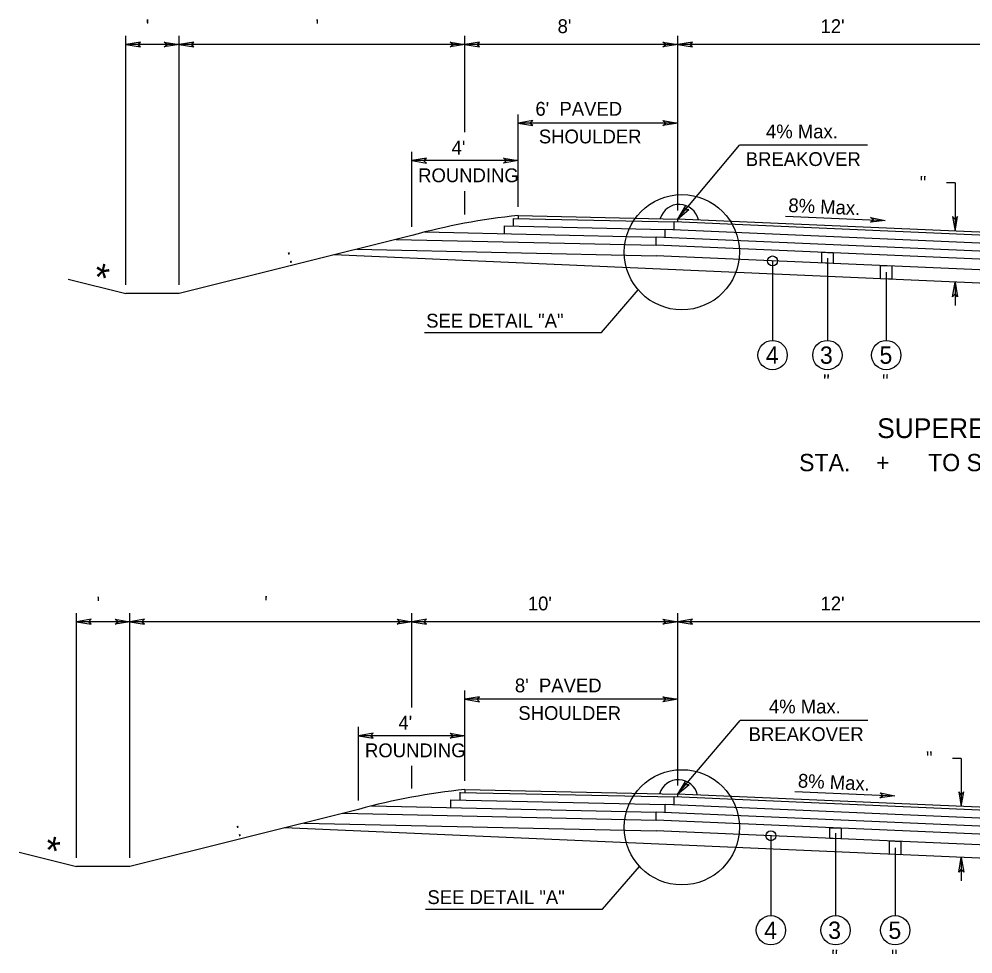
# Model space of a CAD drawing. Extents: x -592 to 1199, y -590 to 416.
# Drawn here: x 991.1 to 1087.7, y -321.9 to -227.2 of the extents above; entities that cross this region are included whole.
import ezdxf

# ---------------------------------------------------------------- set-up
doc = ezdxf.new("R2010")
doc.units = 0
doc.layers.add('1', color=7, linetype='Continuous')
doc.layers.add('Des_ Drain_ Ftrs', color=7, linetype='Continuous')

msp = doc.modelspace()

# ---------------------------------------------------------------- linework, layer by layer
at = {"layer": '1'}
for p, q in [((1001.867, -254.098), (1001.867, -228.863)), ((1007.255, -254.098), (1007.255, -228.863)), ((1036.225, -238.63), (1036.225, -228.863)), ((1057.778, -246.545), (1057.778, -228.863)), ((1007.255, -229.743), (1001.867, -229.743)), ((1036.225, -229.743), (1007.255, -229.743)), ((1057.778, -229.743), (1036.225, -229.743)), ((1090.108, -229.743), (1057.778, -229.743)), ((1041.614, -246.192), (1041.614, -236.824)), ((1057.778, -237.704), (1041.614, -237.704)), ((1057.772, -247.425), (1064.032, -239.951)), ((1077.001, -239.951), (1064.032, -239.951)), ((1030.837, -248.202), (1030.837, -240.628)), ((1041.614, -241.508), (1030.837, -241.508)), ((1085.881, -243.773), (1085.001, -243.773)), ((1085.881, -243.773), (1085.881, -248.652)), ((1036.225, -246.969), (1036.225, -244.588)), ((1041.158, -247.362), (1057.432, -247.71)), ((1041.158, -248.143), (1041.158, -247.362)), ((1041.614, -247.072), (1057.772, -247.425)), ((1041.614, -247.072), (1041.614, -247.372)), ((1068.685, -247.124), (1078.798, -247.565)), ((1040.232, -248.123), (1056.51, -248.479)), ((1040.232, -248.912), (1040.232, -248.123)), ((1090.108, -249.136), (1057.432, -247.71)), ((1057.432, -248.519), (1057.432, -247.71)), ((1090.108, -248.836), (1057.772, -247.425)), ((1057.772, -247.425), (1057.772, -247.725)), ((1030.837, -249.082), (1007.255, -254.978)), ((1032.161, -248.736), (1055.587, -249.248)), ((1090.108, -250.755), (1055.587, -249.248)), ((1055.587, -250.057), (1055.587, -249.248)), ((1090.108, -249.946), (1056.51, -248.479)), ((1056.51, -249.288), (1056.51, -248.479)), ((1029.241, -249.481), (1055.587, -250.057)), ((1090.108, -251.564), (1055.587, -250.057)), ((1090.108, -253.991), (1022.937, -251.057)), ((1025.274, -250.473), (1055.587, -251.135)), ((1090.108, -252.643), (1055.587, -251.135)), ((1067.388, -251.666), (1067.388, -259.723)), ((1072.943, -251.375), (1072.943, -259.723)), ((1078.911, -252.805), (1078.911, -259.723)), ((996.039, -253.521), (1001.867, -254.978)), ((1085.881, -253.804), (1085.881, -256.173)), ((1007.255, -254.978), (1001.867, -254.978)), ((1050.044, -258.923), (1053.784, -254.603)), ((1032.113, -258.923), (1050.044, -258.923)), ((996.88, -312.128), (996.88, -287.33)), ((1002.268, -312.128), (1002.268, -287.33)), ((1030.837, -296.894), (1030.837, -287.33)), ((1057.778, -304.793), (1057.778, -287.33)), ((1002.268, -288.21), (996.88, -288.21)), ((1030.837, -288.21), (1002.268, -288.21)), ((1057.778, -288.21), (1030.837, -288.21)), ((1090.108, -288.21), (1057.778, -288.21)), ((1036.225, -304.322), (1036.225, -295.182)), ((1057.778, -296.062), (1036.225, -296.062)), ((1057.772, -305.673), (1064.117, -298.198)), ((1077.05, -298.198), (1064.117, -298.198)), ((1025.449, -306.333), (1025.449, -298.872)), ((1036.225, -299.752), (1025.449, -299.752)), ((1086.513, -302.048), (1085.633, -302.048)), ((1086.513, -302.048), (1086.513, -306.928)), ((1030.837, -305.1), (1030.837, -302.808)), ((1036.225, -305.202), (1057.772, -305.673)), ((1036.225, -305.202), (1036.225, -305.502)), ((1034.805, -306.253), (1056.51, -306.727)), ((1034.805, -307.042), (1034.805, -306.253)), ((1035.731, -306.273), (1035.731, -305.484)), ((1035.731, -305.492), (1057.432, -305.958)), ((1090.108, -307.385), (1057.432, -305.958)), ((1057.432, -306.767), (1057.432, -305.958)), ((1090.108, -307.085), (1057.772, -305.673)), ((1057.772, -305.673), (1057.772, -305.973)), ((1069.652, -305.416), (1079.765, -305.858)), ((1025.449, -307.213), (1002.268, -313.008)), ((1026.774, -306.866), (1055.587, -307.496)), ((1090.108, -308.194), (1056.51, -306.727)), ((1056.51, -307.536), (1056.51, -306.727)), ((1023.854, -307.612), (1055.587, -308.305)), ((1090.108, -309.003), (1055.587, -307.496)), ((1055.587, -308.305), (1055.587, -307.496)), ((1090.108, -312.239), (1017.951, -309.088)), ((1019.887, -308.604), (1055.587, -309.383)), ((1090.108, -309.812), (1055.587, -308.305)), ((1090.108, -310.891), (1055.587, -309.383)), ((1067.221, -309.89), (1067.221, -317.971)), ((1073.781, -309.636), (1073.781, -317.971)), ((1079.817, -311.106), (1079.817, -317.971)), ((991.053, -311.551), (996.88, -313.008)), ((1086.513, -312.08), (1086.513, -314.448)), ((1002.268, -313.008), (996.88, -313.008)), ((1050.169, -317.31), (1053.908, -312.991)), ((1032.237, -317.31), (1050.169, -317.31))]:
    msp.add_line(p, q, dxfattribs=at)
for points in [[(1072.37, -250.789), (1073.516, -250.839), (1073.516, -251.918), (1072.37, -251.868)], [(1078.337, -252.129), (1079.484, -252.179), (1079.484, -253.527), (1078.337, -253.477)], [(1073.208, -309.074), (1074.354, -309.124), (1074.354, -310.203), (1073.208, -310.153)], [(1079.244, -310.416), (1080.391, -310.466), (1080.391, -311.814), (1079.244, -311.764)]]:
    msp.add_lwpolyline(points, close=True, dxfattribs=at)
for centre, radius in [((1058.199, -250.784), 5.838), ((1067.388, -251.666), 0.5), ((1067.388, -261.208), 1.485), ((1072.943, -261.208), 1.485), ((1078.911, -261.208), 1.485), ((1058.199, -309.032), 5.838), ((1067.221, -309.89), 0.5), ((1067.221, -319.456), 1.485), ((1073.781, -319.456), 1.485), ((1079.817, -319.456), 1.485)]:
    msp.add_circle(centre, radius, dxfattribs=at)
for centre, radius, start, end in [((1057.927, -247.941), 1.996, 12.24797, 163.77001), ((1048.508, -313.905), 67.188, 95.88973, 105.24829), ((1057.852, -306.209), 1.999, 12.95779, 163.16109), ((1043.121, -372.035), 67.188, 95.89109, 105.24966)]:
    msp.add_arc(centre, radius, start, end, dxfattribs=at)
at = {"layer": 'Des_ Drain_ Ftrs'}
for points in [[(1001.867, -229.743), (1003.355, -229.991), (1003.06, -229.743), (1003.355, -229.494)], [(1007.255, -229.743), (1005.767, -229.991), (1006.062, -229.743), (1005.767, -229.494)], [(1007.255, -229.743), (1008.743, -229.991), (1008.448, -229.743), (1008.743, -229.494)], [(1036.225, -229.743), (1034.737, -229.991), (1035.032, -229.743), (1034.737, -229.494)], [(1036.225, -229.743), (1037.714, -229.991), (1037.419, -229.743), (1037.714, -229.494)], [(1057.778, -229.743), (1056.29, -229.991), (1056.585, -229.743), (1056.29, -229.494)], [(1057.778, -229.743), (1059.267, -229.991), (1058.972, -229.743), (1059.267, -229.494)], [(1041.614, -237.704), (1043.102, -237.952), (1042.807, -237.704), (1043.102, -237.455)], [(1057.778, -237.704), (1056.29, -237.952), (1056.585, -237.704), (1056.29, -237.455)], [(1030.837, -241.508), (1032.325, -241.756), (1032.03, -241.508), (1032.325, -241.259)], [(1041.614, -241.508), (1040.125, -241.756), (1040.42, -241.508), (1040.125, -241.259)], [(1057.772, -247.425), (1058.918, -246.443), (1058.538, -246.51), (1058.537, -246.124)], [(1078.798, -247.565), (1077.3, -247.748), (1077.605, -247.513), (1077.322, -247.252)], [(1085.881, -248.652), (1086.129, -247.164), (1085.881, -247.459), (1085.633, -247.164)], [(1085.881, -253.804), (1086.129, -255.293), (1085.881, -254.998), (1085.633, -255.293)], [(996.88, -288.21), (998.369, -288.458), (998.074, -288.21), (998.369, -287.962)], [(1002.268, -288.21), (1000.78, -288.458), (1001.075, -288.21), (1000.78, -287.962)], [(1002.268, -288.21), (1003.757, -288.458), (1003.462, -288.21), (1003.757, -287.962)], [(1030.837, -288.21), (1029.349, -288.458), (1029.644, -288.21), (1029.349, -287.962)], [(1030.837, -288.21), (1032.326, -288.458), (1032.031, -288.21), (1032.326, -287.962)], [(1057.778, -288.21), (1056.29, -288.458), (1056.585, -288.21), (1056.29, -287.962)], [(1057.778, -288.21), (1059.267, -288.458), (1058.972, -288.21), (1059.267, -287.962)], [(1036.225, -296.062), (1037.714, -296.31), (1037.419, -296.062), (1037.714, -295.813)], [(1057.778, -296.062), (1056.29, -296.31), (1056.585, -296.062), (1056.29, -295.813)], [(1025.449, -299.752), (1026.937, -300), (1026.642, -299.752), (1026.937, -299.504)], [(1036.225, -299.752), (1034.737, -300), (1035.032, -299.752), (1034.737, -299.504)], [(1057.772, -305.673), (1058.925, -304.699), (1058.544, -304.763), (1058.546, -304.377)], [(1079.765, -305.858), (1078.267, -306.041), (1078.572, -305.805), (1078.289, -305.545)], [(1086.513, -306.928), (1086.761, -305.439), (1086.513, -305.734), (1086.264, -305.439)], [(1086.513, -312.08), (1086.761, -313.568), (1086.513, -313.273), (1086.264, -313.568)]]:
    msp.add_lwpolyline(points, close=True, dxfattribs=at)

# ---------------------------------------------------------------- texts
at = {"layer": '1'}
for s, height, p in [(" '", 1.4, (1003.366, -228.591)), ("  '", 1.4, (1020.044, -228.591)), ("8'", 1.4, (1045.611, -228.591)), ("12'", 1.4, (1072.249, -228.591)), ("6'  PAVED", 1.4, (1043.363, -236.96)), ('SHOULDER', 1.4, (1043.712, -239.76)), ('4% Max.', 1.4, (1066.723, -239.251)), ("4'", 1.4, (1034.873, -240.892)), ('BREAKOVER', 1.4, (1064.672, -242.051)), ('ROUNDING', 1.4, (1031.484, -243.692)), ('SEE DETAIL "A"', 1.4, (1032.298, -258.42)), ('4', 1.75, (1066.712, -262.083)), ('3', 1.75, (1072.187, -262.083)), ('5', 1.75, (1078.22, -262.083)), (' "', 1.4, (1071.999, -264.568)), (' "', 1.4, (1077.967, -264.568)), ('SUPERELEVATED', 2, (1077.988, -269.607)), ('STA.    +      TO STA.    +     ', 1.75, (1070.078, -272.963)), (" '", 1.4, (998.379, -287.059)), ("  '", 1.4, (1014.857, -286.988)), ("10'", 1.4, (1042.593, -287.059)), ("12'", 1.4, (1072.249, -287.059)), ("8'  PAVED", 1.4, (1041.286, -295.361)), ('4% Max.', 1.4, (1067.019, -297.498)), ('SHOULDER', 1.4, (1041.635, -298.161)), ("4'", 1.4, (1029.485, -299.136)), ('BREAKOVER', 1.4, (1064.968, -300.298)), ('ROUNDING', 1.4, (1026.096, -301.936)), ('SEE DETAIL "A"', 1.4, (1032.422, -316.807)), ('4', 1.75, (1066.546, -320.331)), ('3', 1.75, (1073.025, -320.331)), ('5', 1.75, (1079.126, -320.331)), (' "', 1.4, (1072.837, -322.816)), (' "', 1.4, (1078.874, -322.816))]:
    msp.add_text(s, height=height, dxfattribs=at).set_placement(p)
for s, height, rotation, p in [('  "', 1.4, 0.14377, (1081.268, -244.476)), ('8% Max.', 1.4, 357.37622, (1068.967, -246.707)), (' : ', 1.4, 14.22821, (1017.866, -252.043)), ('*', 2.8, 347.15207, (998.352, -254.546)), ('  "', 1.4, 0.14377, (1081.9, -302.752)), ('8% Max.', 1.4, 357.3762, (1069.934, -304.999)), (' : ', 1.4, 14.22821, (1012.679, -310.123)), ('*', 2.8, 347.15207, (993.365, -312.576))]:
    msp.add_text(s, height=height, rotation=rotation, dxfattribs=at).set_placement(p)

doc.saveas('drawing.dxf')
